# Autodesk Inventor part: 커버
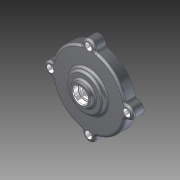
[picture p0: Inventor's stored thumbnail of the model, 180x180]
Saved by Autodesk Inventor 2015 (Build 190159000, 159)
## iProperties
Company: 한국ATC센터
Created: 2014-07
Part Number: 커버
Document SubType Name: 모델링
Designer: KYOUNG IL JANG
Material: Aluminum 6061
Appearance: Aluminum Cast
Mass: 195.931 g
Surface Area: 278.607 cm^2
Volume: 72.5671 cm^3
Density: 2.7 g/cm^3
Author: KYOUNG IL JANG
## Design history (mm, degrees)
revolve "회전1" stored, may be unused: angle "d27" = 90 deg
sketch "스케치2" dims "d29" = 104
  geometry: A1 r 8.5 centre (0, 52) between (8.074, 49.344) and (-8.074, 49.344); A2 r 50 centre (0, 0) between (-8.074, 49.344) and (8.074, 49.344) reference; 2 further points
  constraints: 4 point on circle, 2 vertical alignment, 1 centre point, 1 coincident, 2 other
  dimensions: "d28" = 17 diameter of A1
extrude "돌출1" join sketch "스케치2" stored distance "d30" = 10; taper "d31" = 0 deg
fillet "모깎기3" dims "d32" = 3
fillet "모깎기4" dims "d45" = 3, "d46" = 0.2
chamfer "모따기1" distance "d47" = 1; stored, may be unused: second distance "d48" = 2, angle "d49" = 45 deg
hole "구멍2" diameter "d38" = 5.5; stored, may be unused: countersink angle "d42" = 90 deg, drill point angle "d44" = 118 deg; dims "d36" = 10, "d37" = 10, "d39" = 6, "d40" = 9.5, "d41" = 5.4, "d43" = 8
node "솔리드1"
node "솔리드 본체"
node "곡면 본체"
pattern_circular "원형 패턴1" dims angle "d34" = 360 deg
pattern_circular "원형 패턴2" dims angle "d52" = 360 deg
sketch "스케치1"
  geometry: L1 (0, 0)-(0, 26); L2 (50, 0)-(50, 15); L3 (50, 15)-(25, 15); L4 (25, 15)-(25, 21); L5 (25, 21)-(15, 21); L6 (15, 21)-(13.66, 26); L7 (13.66, 26)-(10, 26); L8 (50, 0)-(45, 0); L9 (45, 0)-(45, 10); L10 (45, 10)-(14.5, 10); L11 (14.5, 10)-(13.266, 3); L12 (13.266, 3)-(11, 3); L13 (11, 3)-(11, 16); L14 (11, 16)-(7.5, 16); L15 (7.5, 16)-(7.5, 19); L16 (7.5, 19)-(10, 19); L17 (10, 19)-(10, 26)
  constraints: 34 end point, 10 parallel, 2 perpendicular, 2 point on line, 1 vertical
  dimensions: "d11" = 100 diameter of L2 L1; "d12" = 22 diameter of L13 L1; "d13" = 90 diameter of L9 L1; "d14" = 15 distance between parallel lines of L3 L8; "d15" = 10 distance between parallel lines of L8 L10; "d16" = 29 diameter of L10.end L1; "d17" = 100 deg angle of L11 L10; "d18" = 7 distance between parallel lines of L12 L10; "d19" = 13 distance between parallel lines of L14 L12; "d20" = 3 distance between parallel lines of L16 L14; "d21" = 15 diameter of L15 L1; "d22" = 20 diameter of L17 L1; "d23" = 30 diameter of L5.end L1; "d24" = 6 distance between parallel lines of L5 L3; "d25" = 50 diameter of L4 L1; "d26" = 105 deg angle of L5 L6; "d50" = 26 distance of L1.start L1.end
node "솔리드2"
